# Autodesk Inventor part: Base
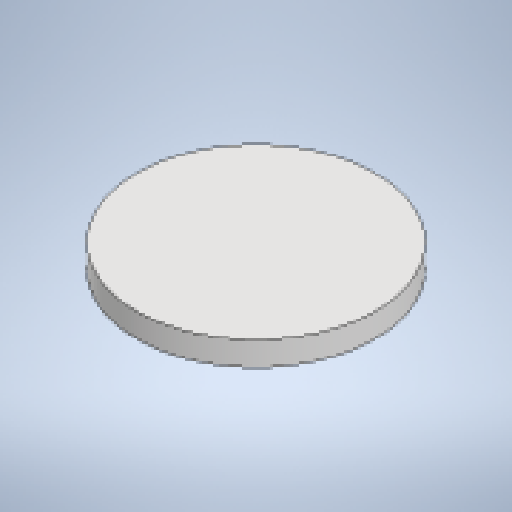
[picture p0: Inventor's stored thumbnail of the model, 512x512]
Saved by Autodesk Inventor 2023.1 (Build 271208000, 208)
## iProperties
Created: 2022-08
Part Number: Base
Material: Generic
Document SubType Name: Modeling
Designer: milos
Density: 1 g/cm^3
Appearance: Default
Author: milos
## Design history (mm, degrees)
sketch "Sketch1"
  geometry: C1 r 5 at (0, 0); 1 further point
  constraints: 1 centre point, 1 coincident
  dimensions: "d0" = 10 diameter of C1
extrude "Extrusion1" new body sketch "Sketch1" distance "d1" = 1; taper "d2" = 0 deg
body "Solid1"
